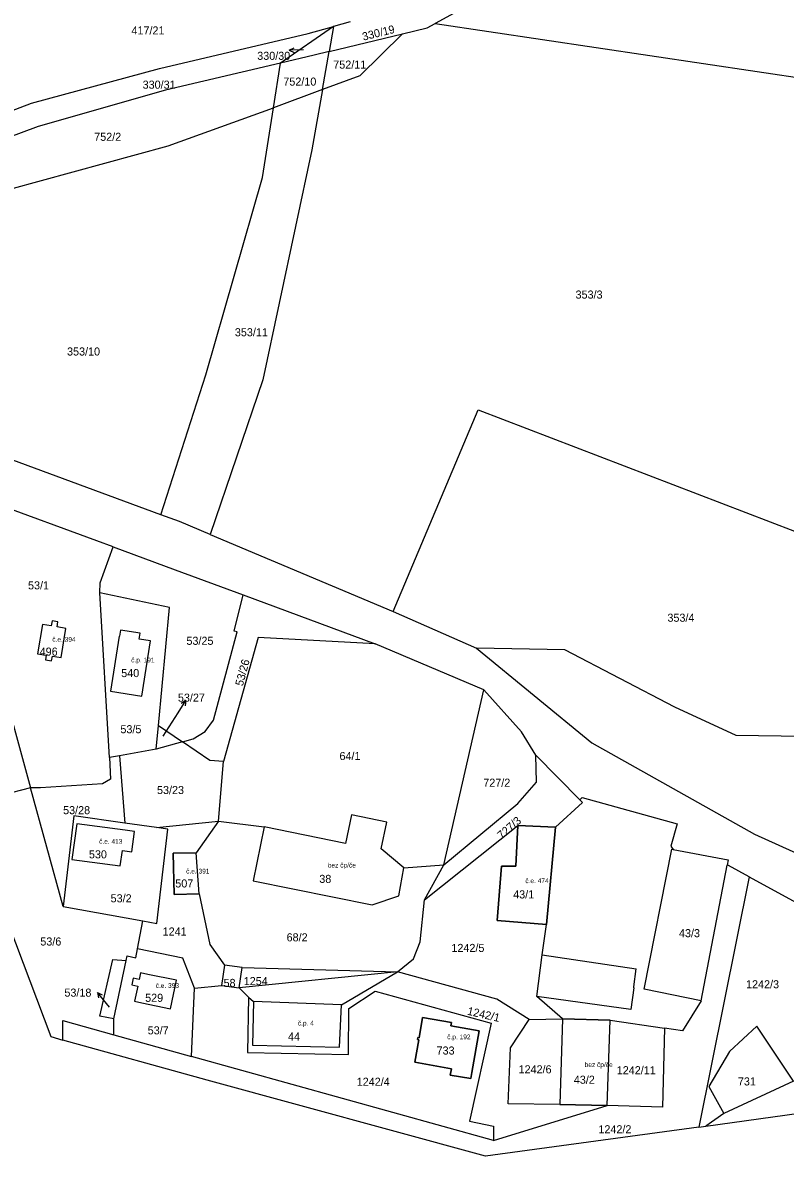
# Model space of a CAD drawing. Extents: x -887272 to -880188, y -1026687 to -1021896.
# Drawn here: x -882976.6 to -882815.9, y -1024101.6 to -1023862.8 of the extents above; entities that cross this region are included whole.
import ezdxf

# ---------------------------------------------------------------- set-up
doc = ezdxf.new("R2010")
doc.units = 0
for name, color, linetype in [('Definiční body', 7, 'Continuous'), ('Hranice parcel', 7, 'Continuous'), ('Parcelní čísla', 7, 'Continuous'), ('Polygon budovy', 7, 'Continuous'), ('Pop  PČ popisy', 7, 'Continuous'), ('Vnitřní kresba', 7, 'Continuous')]:
    doc.layers.add(name, color=color, linetype=linetype)

msp = doc.modelspace()

# ---------------------------------------------------------------- linework, layer by layer
at = {"layer": 'Hranice parcel'}
for p, q in [((-882911.11, -1023863.59), (-882922.29, -1023871.33)), ((-882916.42, -1023865.07), (-882911.11, -1023863.59)), ((-882911.11, -1023863.59), (-882912.04, -1023868.89)), ((-882907.61, -1023862.61), (-882911.11, -1023863.59)), ((-882889.66, -1023862.97), (-882740.58, -1023885.14)), ((-882912.04, -1023868.89), (-882896.59, -1023865.16)), ((-882896.59, -1023865.16), (-882905.58, -1023874)), ((-882912.04, -1023868.89), (-882915.14, -1023869.64)), ((-882913.45, -1023876.9), (-882912.04, -1023868.89)), ((-882923.77, -1023880.71), (-882922.29, -1023871.33)), ((-882915.14, -1023869.64), (-882922.29, -1023871.33)), ((-882905.58, -1023874), (-882913.45, -1023876.9)), ((-882913.45, -1023876.9), (-882923.77, -1023880.71)), ((-882945.96, -1023888.71), (-882923.77, -1023880.71)), ((-882947.44, -1023966.47), (-882938.02, -1023936.95)), ((-882947.44, -1023966.47), (-882999.02, -1023947.42)), ((-882943.56, -1023967.9), (-882947.44, -1023966.47)), ((-882937.06, -1023970.63), (-882943.56, -1023967.9)), ((-882937.06, -1023970.63), (-882898.5, -1023986.86)), ((-882986.9, -1023980.38), (-882974.9, -1024023.97)), ((-882958.29, -1024017.63), (-882960.3, -1023982.89)), ((-882930.15, -1023983.35), (-882902.29, -1023993.66)), ((-882898.5, -1023986.86), (-882881, -1023994.54)), ((-882879.44, -1024003.37), (-882902.29, -1023993.66)), ((-882887.84, -1024040.22), (-882879.44, -1024003.37)), ((-882948.46, -1024015.81), (-882947.99, -1024010.88)), ((-882947.99, -1024010.88), (-882942.92, -1024014.31)), ((-882942.92, -1024014.31), (-882948.46, -1024015.81)), ((-882942.92, -1024014.31), (-882940.69, -1024013.7)), ((-882937.16, -1024018.21), (-882942.92, -1024014.31)), ((-882948.46, -1024015.81), (-882956.15, -1024017.23)), ((-882956.15, -1024017.23), (-882958.29, -1024017.63)), ((-882956.15, -1024017.23), (-882955.08, -1024031.41)), ((-882934.25, -1024018.45), (-882937.16, -1024018.21)), ((-882935.36, -1024031), (-882934.25, -1024018.45)), ((-882859.19, -1024026.51), (-882868.46, -1024017.12)), ((-882974.9, -1024023.97), (-882980.91, -1024025.5)), ((-882968.02, -1024048.98), (-882974.9, -1024023.97)), ((-882972.85, -1024023.97), (-882974.9, -1024023.97)), ((-882859.19, -1024026.51), (-882858.74, -1024026.06)), ((-882948.36, -1024032.37), (-882935.36, -1024031)), ((-882935.36, -1024031), (-882940.06, -1024037.66)), ((-882935.36, -1024031), (-882925.68, -1024032.22)), ((-882948.36, -1024032.37), (-882955.08, -1024031.41)), ((-882891.9, -1024047.58), (-882872.26, -1024031.9)), ((-882944.88, -1024037.77), (-882940.06, -1024037.66)), ((-882944.68, -1024046.47), (-882944.88, -1024037.77)), ((-882939.43, -1024046.3), (-882940.06, -1024037.66)), ((-882839.57, -1024036.96), (-882827.96, -1024039.18)), ((-882896.32, -1024040.84), (-882887.84, -1024040.22)), ((-882891.9, -1024047.58), (-882887.84, -1024040.22)), ((-882833.66, -1024068.88), (-882828.18, -1024040.29)), ((-882827.96, -1024039.18), (-882828.18, -1024040.29)), ((-882823.53, -1024042.74), (-882834.12, -1024095.48)), ((-882823.53, -1024042.74), (-882793.44, -1024059.16)), ((-882939.43, -1024046.3), (-882944.68, -1024046.47)), ((-882968.02, -1024048.98), (-882951.29, -1024052.03)), ((-882952.42, -1024057.94), (-882951.29, -1024052.03)), ((-882979.5, -1024052.93), (-882970.63, -1024076.39)), ((-882954.78, -1024060.37), (-882954.57, -1024059.39)), ((-882957.34, -1024072.67), (-882954.78, -1024060.37)), ((-882934.05, -1024061.34), (-882934.66, -1024065.61)), ((-882930.35, -1024061.87), (-882934.05, -1024061.34)), ((-882930.96, -1024066.14), (-882930.35, -1024061.87)), ((-882930.35, -1024061.87), (-882897.65, -1024062.74)), ((-882897.65, -1024062.74), (-882930.96, -1024066.14)), ((-882940.98, -1024080.58), (-882940.36, -1024066.16)), ((-882940.36, -1024066.16), (-882934.66, -1024065.61)), ((-882934.66, -1024065.61), (-882930.96, -1024066.14)), ((-882930.96, -1024066.14), (-882929.03, -1024068.12)), ((-882833.66, -1024068.88), (-882845.63, -1024066.38)), ((-882929.03, -1024068.12), (-882927.92, -1024068.99)), ((-882957.35, -1024076.01), (-882957.34, -1024072.67)), ((-882869.92, -1024072.76), (-882862.86, -1024072.65)), ((-882862.86, -1024072.65), (-882863.45, -1024090.67)), ((-882862.86, -1024072.65), (-882852.82, -1024072.93)), ((-882853.42, -1024090.93), (-882852.82, -1024072.93)), ((-882852.82, -1024072.93), (-882841.37, -1024074.62)), ((-882970.63, -1024076.39), (-882968.15, -1024077.18)), ((-882957.35, -1024076.01), (-882940.98, -1024080.58)), ((-882841.37, -1024074.62), (-882841.8, -1024091.23)), ((-882877.4, -1024098.3), (-882940.98, -1024080.58)), ((-882814.22, -1024085.76), (-882828.88, -1024092.62)), ((-882877.4, -1024098.3), (-882853.42, -1024090.93)), ((-882853.42, -1024090.93), (-882863.45, -1024090.67)), ((-882841.8, -1024091.23), (-882853.42, -1024090.93)), ((-882832.64, -1024095.28), (-882813.04, -1024092.5)), ((-882828.88, -1024092.62), (-882832.64, -1024095.28)), ((-882834.12, -1024095.48), (-882832.64, -1024095.28))]:
    msp.add_line(p, q, dxfattribs=at)
for points in [[(-882814.51, -1023804.61), (-882840.14, -1023827.98), (-882853.74, -1023840.13), (-882872.92, -1023853.76), (-882889.66, -1023862.97)], [(-882896.59, -1023865.16), (-882891.36, -1023863.9), (-882889.66, -1023862.97)], [(-883000.47, -1023892.28), (-882988.57, -1023885.01), (-882974.72, -1023879.72), (-882947.73, -1023872.42), (-882916.42, -1023865.07)], [(-882922.29, -1023871.33), (-882946.52, -1023877.04), (-882973.33, -1023884.65), (-882986.6, -1023889.58), (-882996.92, -1023895.29), (-883006.13, -1023904.79)], [(-882913.45, -1023876.9), (-882915.68, -1023889.6), (-882926, -1023938.04), (-882937.06, -1023970.63)], [(-882938.02, -1023936.95), (-882926.08, -1023895.38), (-882923.77, -1023880.71)], [(-882999.02, -1023947.42), (-882994.2, -1023935.08), (-882996.98, -1023921.26), (-882992.7, -1023901.52), (-882945.96, -1023888.71)], [(-882898.5, -1023986.86), (-882880.66, -1023944.34), (-882783.22, -1023981.7)], [(-882957.52, -1023973.24), (-882960.99, -1023971.96), (-882982.44, -1023964.11)], [(-882960.3, -1023982.89), (-882960.28, -1023980.77), (-882957.52, -1023973.24)], [(-882957.52, -1023973.24), (-882944.43, -1023978.08), (-882930.15, -1023983.35)], [(-882947.99, -1024010.88), (-882945.62, -1023985.99), (-882960.3, -1023982.89)], [(-882940.69, -1024013.7), (-882938.13, -1024012.12), (-882936.36, -1024009.73), (-882931.42, -1023991.11), (-882932.04, -1023990.98), (-882930.15, -1023983.35)], [(-882973.42, -1023995.74), (-882971.6, -1023996.04), (-882971.76, -1023997.03), (-882970.48, -1023997.24), (-882970.32, -1023996.26), (-882968.5, -1023996.56), (-882967.47, -1023990.41), (-882969.34, -1023990.1), (-882969.16, -1023989), (-882970.39, -1023988.79), (-882970.57, -1023989.89), (-882972.39, -1023989.59), (-882973.42, -1023995.74)], [(-882952.01, -1023992.68), (-882951.81, -1023991.4), (-882955.98, -1023990.75), (-882956.18, -1023992.03), (-882956.28, -1023992.02), (-882958.08, -1024003.61), (-882951.46, -1024004.66), (-882949.64, -1023993.05), (-882952.01, -1023992.68)], [(-882902.29, -1023993.66), (-882927, -1023992.35), (-882934.25, -1024018.45)], [(-882793.94, -1024015.04), (-882803.56, -1024013.88), (-882812.08, -1024013.2), (-882826.3, -1024012.98), (-882839.2, -1024006.98), (-882862.38, -1023994.9), (-882881, -1023994.54)], [(-882881, -1023994.54), (-882856.7, -1024014.52), (-882822.42, -1024033.78), (-882792.42, -1024047.32), (-882777.72, -1024049.62), (-882760.86, -1024047.48), (-882725.1, -1024045.88)], [(-882868.46, -1024017.12), (-882871.52, -1024012.16), (-882879.44, -1024003.37)], [(-882958.29, -1024017.63), (-882958.05, -1024022.19), (-882959.79, -1024023.14), (-882972.85, -1024023.97)], [(-882887.84, -1024040.22), (-882872.24, -1024027.26), (-882868.34, -1024022.78), (-882868.46, -1024017.12)], [(-882872.26, -1024031.9), (-882864.37, -1024032.3), (-882858.64, -1024027.06), (-882859.19, -1024026.51)], [(-882858.74, -1024026.06), (-882838.7, -1024031.6), (-882840.05, -1024036.3), (-882839.57, -1024036.96)], [(-882955.08, -1024031.41), (-882965.78, -1024029.88), (-882968.02, -1024048.98)], [(-882896.32, -1024040.84), (-882901.04, -1024036.87), (-882899.89, -1024031.19), (-882907.33, -1024029.68), (-882908.55, -1024035.7), (-882925.68, -1024032.22)], [(-882965.17, -1024031.59), (-882966.2, -1024039.11), (-882956.01, -1024040.44), (-882955.57, -1024037.21), (-882953.61, -1024037.48), (-882953.04, -1024033.19), (-882954.99, -1024032.93), (-882965.17, -1024031.59)], [(-882951.29, -1024052.03), (-882948.35, -1024052.57), (-882945.98, -1024032.71), (-882948.36, -1024032.37)], [(-882925.68, -1024032.22), (-882928, -1024043.61), (-882902.98, -1024048.66)], [(-882862.86, -1024072.65), (-882868.28, -1024067.96), (-882867.18, -1024059.2), (-882866.22, -1024052.8), (-882876.6, -1024051.94), (-882875.68, -1024040.48), (-882872.72, -1024040.5), (-882872.26, -1024031.9)], [(-882845.63, -1024066.38), (-882839.81, -1024036.91), (-882839.57, -1024036.96)], [(-882902.98, -1024048.66), (-882897.34, -1024046.75), (-882896.32, -1024040.84)], [(-882823.53, -1024042.74), (-882827.92, -1024040.34), (-882828.18, -1024040.29)], [(-882939.43, -1024046.3), (-882937.18, -1024057.02), (-882934.05, -1024061.34)], [(-882897.65, -1024062.74), (-882894.28, -1024059.98), (-882892.84, -1024056.4), (-882891.9, -1024047.58)], [(-882954.57, -1024059.39), (-882952.77, -1024059.77), (-882952.42, -1024057.94)], [(-882940.36, -1024066.16), (-882942.84, -1024059.86), (-882952.42, -1024057.94)], [(-882957.34, -1024072.67), (-882960.29, -1024072.11), (-882957.57, -1024060.17), (-882954.78, -1024060.37)], [(-882951.49, -1024069.25), (-882945.45, -1024070.55), (-882944.15, -1024064.53), (-882950.18, -1024063.29), (-882951.74, -1024062.97), (-882952.04, -1024064.37), (-882953.3, -1024064.1), (-882953.61, -1024065.5), (-882952.35, -1024065.78), (-882953.03, -1024068.92), (-882951.49, -1024069.25)], [(-882909.85, -1024078.65), (-882909.39, -1024069.72), (-882897.65, -1024062.74)], [(-882869.92, -1024072.76), (-882876.73, -1024068.53), (-882897.65, -1024062.74)], [(-882929.03, -1024068.12), (-882929.25, -1024079.78), (-882907.96, -1024080.18), (-882907.89, -1024070.47), (-882902.29, -1024066.85), (-882877.91, -1024073.57), (-882882.43, -1024094.22), (-882877.41, -1024095.29), (-882877.4, -1024098.3)], [(-882927.92, -1024068.99), (-882928.16, -1024078.19), (-882909.85, -1024078.65)], [(-882833.66, -1024068.88), (-882837.6, -1024075.18), (-882841.37, -1024074.62)], [(-882968.15, -1024077.18), (-882968.13, -1024073.01), (-882957.35, -1024076.01)], [(-882893.33, -1024076.6), (-882893.09, -1024076.64), (-882892.35, -1024072.4), (-882886.27, -1024073.45), (-882886.38, -1024074.13), (-882880.42, -1024075.2), (-882881.93, -1024083.97), (-882882.15, -1024085.24), (-882886.52, -1024084.53), (-882886.28, -1024083.18), (-882893.99, -1024081.78), (-882893.16, -1024077.05), (-882893.4, -1024077.01), (-882893.33, -1024076.6)], [(-882863.45, -1024090.67), (-882874.34, -1024090.56), (-882873.85, -1024078.79), (-882869.92, -1024072.76)], [(-882814.22, -1024085.76), (-882821.92, -1024074.22), (-882827.7, -1024079.54), (-882832.06, -1024086.88), (-882828.88, -1024092.62)], [(-882834.12, -1024095.48), (-882879.1, -1024101.62), (-882937.74, -1024085.6), (-882968.15, -1024077.18)]]:
    msp.add_lwpolyline(points, dxfattribs=at)
at = {"layer": 'Polygon budovy'}
for points in [[(-882972.39, -1023989.59), (-882973.42, -1023995.74), (-882971.6, -1023996.04), (-882971.76, -1023997.03), (-882970.48, -1023997.24), (-882970.32, -1023996.26), (-882968.5, -1023996.56), (-882967.47, -1023990.41), (-882969.34, -1023990.1), (-882969.16, -1023989), (-882970.39, -1023988.79), (-882970.57, -1023989.89)], [(-882958.08, -1024003.61), (-882951.46, -1024004.66), (-882949.64, -1023993.05), (-882952.01, -1023992.68), (-882951.81, -1023991.4), (-882955.98, -1023990.75), (-882956.18, -1023992.03), (-882956.28, -1023992.02)], [(-882928, -1024043.61), (-882902.98, -1024048.66), (-882897.34, -1024046.75), (-882896.32, -1024040.84), (-882901.04, -1024036.87), (-882899.89, -1024031.19), (-882907.33, -1024029.68), (-882908.55, -1024035.7), (-882925.68, -1024032.22)], [(-882965.17, -1024031.59), (-882966.2, -1024039.11), (-882956.01, -1024040.44), (-882955.57, -1024037.21), (-882953.61, -1024037.48), (-882953.04, -1024033.19), (-882954.99, -1024032.93)], [(-882872.72, -1024040.5), (-882875.68, -1024040.48), (-882876.6, -1024051.94), (-882866.22, -1024052.8), (-882864.37, -1024032.3), (-882872.26, -1024031.9)], [(-882940.06, -1024037.66), (-882944.88, -1024037.77), (-882944.68, -1024046.47), (-882939.43, -1024046.3)], [(-882944.15, -1024064.53), (-882950.18, -1024063.29), (-882951.74, -1024062.97), (-882952.04, -1024064.37), (-882953.3, -1024064.1), (-882953.61, -1024065.5), (-882952.35, -1024065.78), (-882953.03, -1024068.92), (-882951.49, -1024069.25), (-882945.45, -1024070.55)], [(-882927.92, -1024068.99), (-882928.16, -1024078.19), (-882909.85, -1024078.65), (-882909.39, -1024069.72)], [(-882893.99, -1024081.78), (-882886.28, -1024083.18), (-882886.52, -1024084.53), (-882882.15, -1024085.24), (-882881.93, -1024083.97), (-882880.42, -1024075.2), (-882886.38, -1024074.13), (-882886.27, -1024073.45), (-882892.35, -1024072.4), (-882893.09, -1024076.64), (-882893.33, -1024076.6), (-882893.4, -1024077.01), (-882893.16, -1024077.05)], [(-882862.86, -1024072.65), (-882863.45, -1024090.67), (-882853.42, -1024090.93), (-882852.82, -1024072.93)]]:
    msp.add_lwpolyline(points, close=True, dxfattribs=at)
at = {"layer": 'Pop  PČ popisy'}
for p, q in [((-882920.41, -1023868.58), (-882919.42, -1023868.06)), ((-882917.41, -1023868.53), (-882920.41, -1023868.58)), ((-882920.41, -1023868.58), (-882919.4, -1023869.07)), ((-882943.81, -1024008.16), (-882942.22, -1024005.61)), ((-882942.22, -1024005.61), (-882943.18, -1024006.2)), ((-882942.22, -1024005.61), (-882942.33, -1024006.73)), ((-882946.95, -1024013.12), (-882943.81, -1024008.16)), ((-882958.94, -1024069.45), (-882960.83, -1024067.12)), ((-882960.83, -1024067.12), (-882959.81, -1024067.58)), ((-882960.83, -1024067.12), (-882960.59, -1024068.21)), ((-882958.31, -1024070.22), (-882958.94, -1024069.45))]:
    msp.add_line(p, q, dxfattribs=at)
at = {"layer": 'Vnitřní kresba'}
for p, q in [((-882864.37, -1024032.3), (-882866.22, -1024052.8)), ((-882867.18, -1024059.2), (-882847.32, -1024062.1)), ((-882847.82, -1024065.92), (-882847.32, -1024062.1)), ((-882847.84, -1024066.1), (-882848.44, -1024070.72)), ((-882847.84, -1024066.1), (-882847.82, -1024065.92)), ((-882909.39, -1024069.72), (-882927.92, -1024068.99)), ((-882848.44, -1024070.72), (-882868.28, -1024067.96))]:
    msp.add_line(p, q, dxfattribs=at)

# ---------------------------------------------------------------- texts
at = {"layer": 'Definiční body'}
for s, p in [('č.e. 394', (-882970.34, -1023993.21)), ('č.p. 191', (-882953.72, -1023997.56)), ('č.e. 413', (-882960.47, -1024035.77)), ('bez čp/če', (-882912.3, -1024040.79)), ('č.e. 391', (-882942.14, -1024042.04)), ('č.e. 474', (-882870.7, -1024044.07)), ('č.e. 393', (-882948.56, -1024066.13)), ('č.p. 4', (-882918.61, -1024074.06)), ('č.p. 192', (-882887.15, -1024076.96)), ('bez čp/če', (-882858.19, -1024082.82))]:
    msp.add_text(s, height=1, dxfattribs=at).set_placement(p)
at = {"layer": 'Parcelní čísla'}
for s, p in [('417/21', (-882953.66, -1023865.28)), ('330/30', (-882927.17, -1023870.62)), ('752/11', (-882911.15, -1023872.47)), ('330/31', (-882951.31, -1023876.7)), ('752/10', (-882921.67, -1023876.05)), ('752/2', (-882961.51, -1023887.68)), ('353/3', (-882860.11, -1023920.92)), ('353/11', (-882931.88, -1023928.86)), ('353/10', (-882967.23, -1023932.91)), ('53/1', (-882975.45, -1023982.18)), ('353/4', (-882840.76, -1023989)), ('53/25', (-882942.08, -1023993.86)), ('496', (-882973, -1023996.14)), ('540', (-882955.82, -1024000.66)), ('53/27', (-882943.88, -1024005.84)), ('53/5', (-882955.99, -1024012.49)), ('64/1', (-882909.84, -1024018.13)), ('53/23', (-882948.28, -1024025.3)), ('727/2', (-882879.55, -1024023.76)), ('53/28', (-882968.06, -1024029.54)), ('530', (-882962.62, -1024038.85)), ('507', (-882944.43, -1024044.98)), ('38', (-882914.09, -1024044.02)), ('43/1', (-882873.25, -1024047.29)), ('53/2', (-882958.05, -1024048.11)), ('1241', (-882947.09, -1024055.11)), ('68/2', (-882920.98, -1024056.33)), ('43/3', (-882838.33, -1024055.46)), ('53/6', (-882972.86, -1024057.21)), ('1242/5', (-882886.27, -1024058.57)), ('58', (-882934.26, -1024065.94)), ('1254', (-882930.01, -1024065.55)), ('1242/3', (-882824.2, -1024066.22)), ('53/18', (-882967.79, -1024067.98)), ('529', (-882950.78, -1024069.07)), ('53/7', (-882950.24, -1024075.93)), ('44', (-882920.67, -1024077.22)), ('733', (-882889.39, -1024080.18)), ('1242/6', (-882872.12, -1024084.14)), ('1242/11', (-882851.44, -1024084.33)), ('1242/4', (-882906.21, -1024086.76)), ('43/2', (-882860.48, -1024086.33)), ('731', (-882825.92, -1024086.69)), ('1242/2', (-882855.3, -1024096.77))]:
    msp.add_text(s, height=1.7, dxfattribs=at).set_placement(p)
for s, rotation, p in [('330/19', 14, (-882904.81, -1023866.59)), ('53/26', 75, (-882930.21, -1024002.66)), ('727/3', 41, (-882875.68, -1024034.89)), ('1242/1', 347, (-882883.04, -1024071.76))]:
    msp.add_text(s, height=1.7, rotation=rotation, dxfattribs=at).set_placement(p)

doc.saveas('drawing.dxf')
